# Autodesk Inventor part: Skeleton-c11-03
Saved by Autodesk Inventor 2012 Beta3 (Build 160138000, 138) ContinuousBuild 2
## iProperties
Created: 2011-01
Part Number: Skeleton-c11-03
Material: Default
Document SubType Name: Modeling
Designer: Beta-8540w
Density: 1 g/cm^3
_SkeletonDoc: Frame Skeleton File
_Version: 15.0.0
Author: Beta-8540w
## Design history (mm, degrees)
sketch "Reference Skeleton"
